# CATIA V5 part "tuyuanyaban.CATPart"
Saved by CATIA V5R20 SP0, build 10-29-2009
Part number: 凸缘压板
Material "Steel": density 7860 kg/m3, Young's modulus 2e+11 Pa, Poisson ratio 0.266, thermal expansion 1.17e-05 1/K
Bounding box of the stored display mesh (mm): x -40 to 40, y -20 to 20, z -25 to 25
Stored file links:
  F:\CATIA\XLW\tuyuanyaban.CATPart
  D:\CATIA\intel_a\startup\materials\Catalog.CATMaterial
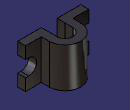
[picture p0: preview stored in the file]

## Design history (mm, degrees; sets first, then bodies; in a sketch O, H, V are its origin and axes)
Body1 (main body), material "Steel"
  Sketch1 on xy-plane, origin (0, 0, 0), H (1, 0, 0), V (0, 1, 0)
    arc A1 centre (0, 0) radius 10 from (10, 0) to (-10, 0) ccw
    arc A2 centre (0, 0) radius 20 from (20, 0) to (-20, 0) ccw
    point P1 (0, -15)
    line L1 (40, -10) -> (40, -20)
    line L2 (40, -20) -> (10, -20)
    line L3 (-40, -20) -> (-40, -10)
    line L4 (-40, -10) -> (-20, -10)
    point P6 (0, -17.1699)
    line L5 (20, 0) -> (20, -10)
    line L6 (-20, -10) -> (-20, 0)
    point P8 (-20, 0)
    line L7 (10, 0) -> (10, -10)
    line L8 (-10, -10) -> (-10, 0)
    point P10 (-10, 0)
    point P11 (-10, 0)
    point P13 (20, -10)
    point P14 (10, -10)
    point P15 (-10, -10)
    line L9 (20, -10) -> (40, -10)
    line L10 (-10, -10) -> (-10, -20)
    point P16 (-10, -20)
    line L11 (10, -10) -> (10, -20)
    line L12 (-10, -20) -> (-40, -20)
    radius A1 = 10
    radius A2 = 20
    distance L3 L1 = 80
    distance L4 L12 = 10
    distance L12 O = 20
    coincidence: P1 V, P6 V, P8 H, L4 P13, L4 P14, L4 P15, L4 L9, P16 L2, L2 L12, P10 P11
    vertical: L1 V, L3 V, L5 V, L6 V, L7 V, L8 V
    horizontal: L2 H, L4 H, L9 H, L12 H
    equidistance: L1 L3 P1, L2 L4 P1, L5 L6 P6, L7 L8 P6
    tangency: L10 A1, L11 A1
  Pad1: profile Sketch1, direction (0, 0, 1), length 25, mirrored extent
  Sketch2 on face of Pad1 from Sketch1.L4, origin (0, -10, 0), H (-1, 0, 0), V (0, 0, 1)
    arc A1 centre (36, 0) radius 10 from (36, 10) to (36, -10) ccw
    point P1 (36, 0)
    line L1 (36, 10) -> (48, 10)
    line L2 (48, 10) -> (48, -10)
    line L3 (48, -10) -> (36, -10)
    radius A1 = 10
    length L2 = 20
    length L3 = 12
    distance V P1 = 36
    coincidence: P1 H
    tangency: L1 A1, L3 A1
    vertical: L2 V
    horizontal: L3 H
  Pocket1: profile Sketch2, direction (0, -1, 0), through (limit type 3)
  Mirror1: of Pocket1, about yz-plane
